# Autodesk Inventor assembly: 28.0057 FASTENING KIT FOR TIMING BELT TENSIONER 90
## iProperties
Created: 2007-06
Part Number: 28.0057 FASTENING KIT FOR TIMING BELT TENSIONER 90
Document SubType Name: Assembly
Designer: Andy Moles
Author: Andy Moles
